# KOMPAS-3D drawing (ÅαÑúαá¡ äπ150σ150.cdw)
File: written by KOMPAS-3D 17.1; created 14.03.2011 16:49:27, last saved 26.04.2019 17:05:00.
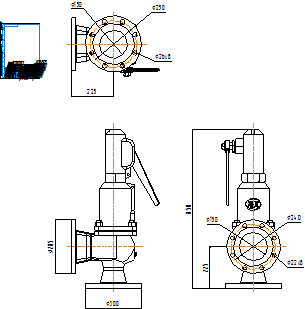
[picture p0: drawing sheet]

Sheet 1: A4, portrait

Title block, sheet 1: name: Прегран Ду150х150; material: Внимание! Данный продукт является объектом авторского права ООО «Торговый Дом АДЛ». / Запрещается изменение, копирование, распространение / (в том числе путем копирования на другие сайты и ресурсы в Интернете) / или любое иное использование информации и объектов без предварительного / согласия правообладателя (ООО «Торговый Дом АДЛ»).; scale: 1:1; sheets: 1; organisation: ООО "Торговый дом АДЛ"; sheet format: A4; stored path: C:\Users\tra\Desktop\2д чертежи\Предохранительные клапаны ПРЕГРАН\ПРЕГРАН 096\ПРЕГРАН КПП 096-03-40\KOMPAS 2D\Прегран Ду150х150.cdw

Views: Проекционный вид 3, Проекционный вид 4, Проекционный вид 5
Dimensions and other numbers on the sheet: 225; 850; 300; 285; 240; 22; 150; 250; 26; 1:1; 1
